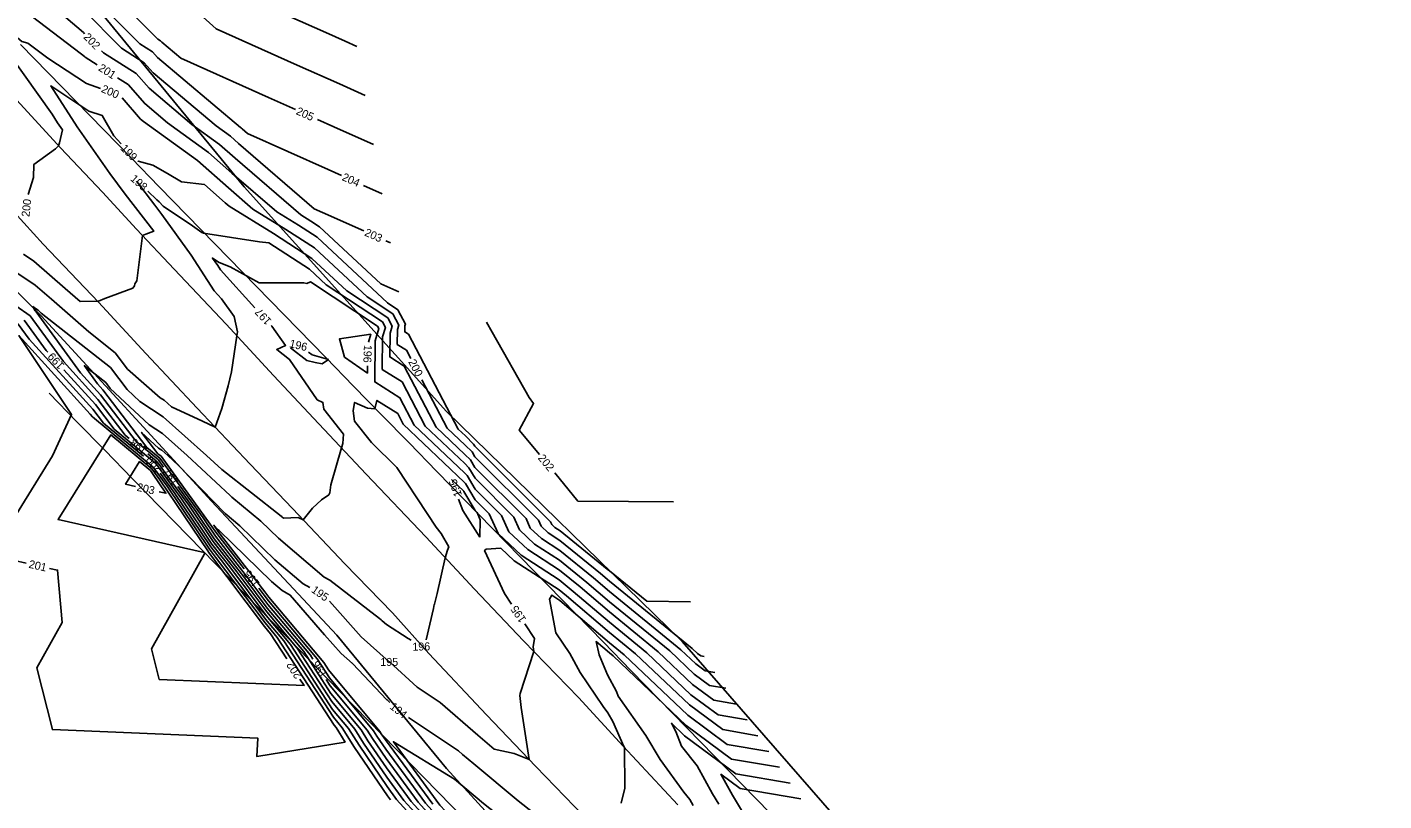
# Model space of a CAD drawing. Extents: x 2086416 to 2115205, y 575507 to 632762.
# Drawn here: x 2110120.8 to 2110459.9, y 582081.1 to 582274.4 of the extents above; entities that cross this region are included whole.
import ezdxf

# ---------------------------------------------------------------- set-up
doc = ezdxf.new("R2010")
doc.units = 0
for name, color, linetype in [('DTM Contours Major', 7, 'Continuous'), ('DTM Contours Major Text', 7, 'Continuous'), ('DTM Contours Minor', 7, 'Continuous'), ('DTM Contours Minor Text', 7, 'Continuous'), ('Exist Hydrographic FEMA Cross Section', 7, 'Continuous'), ('Exist Roads EOP', 7, 'Continuous'), ('Exist Vegetation Woods Line', 7, 'Continuous')]:
    doc.layers.add(name, color=color, linetype=linetype)

msp = doc.modelspace()

# ---------------------------------------------------------------- linework, layer by layer
at = {"layer": 'DTM Contours Major'}
for points in [[(2110109.16, 582313.08), (2110112.32, 582311.02), (2110129.31, 582294.29), (2110131.09, 582292.62), (2110132.72, 582292.09), (2110134.17, 582290.85), (2110153.5, 582271.34), (2110154.17, 582270.92), (2110154.43, 582270.61), (2110159.2, 582266.6), (2110181.16, 582256.77), (2110187.89, 582253.76)], [(2110139.1, 582259.08), (2110135.66, 582260.25), (2110126, 582266.59), (2110120.98, 582270.39), (2110119.48, 582270.82), (2110107.88, 582280.62), (2110107.79, 582280.67), (2110107.65, 582280.8), (2110106.39, 582281.73), (2110107.13, 582280.82), (2110107.89, 582279.73), (2110116.56, 582267.38), (2110127.02, 582252.6), (2110128.41, 582250.45), (2110129.6, 582248.74), (2110128.93, 582245.49), (2110128.68, 582244.73), (2110127.92, 582243.98), (2110122.51, 582240.09), (2110122.35, 582236.81), (2110121.07, 582232.55)], [(2110216.68, 582191.59), (2110215.58, 582193.69), (2110213.31, 582195.12), (2110213.35, 582198.82), (2110213.67, 582199.92), (2110212.19, 582202.73), (2110205.75, 582206.99), (2110192.62, 582219.23), (2110185.46, 582223.85), (2110177.23, 582228.94), (2110171.12, 582234.2), (2110163.38, 582241.04), (2110149.85, 582250.84), (2110149.16, 582251.42), (2110144.51, 582256.72)], [(2110193.36, 582251.31), (2110197.45, 582249.48), (2110207.4, 582245.02)], [(2110086.65, 582243.38), (2110095.68, 582232.16), (2110101, 582226.63), (2110106.9, 582218.72), (2110109.82, 582215.75), (2110111.89, 582209.48), (2110116.13, 582201.87), (2110118.59, 582200.15), (2110121.31, 582196.4), (2110137.22, 582178.92), (2110139.86, 582175.47), (2110149.85, 582167.21)], [(2110290, 582117.14), (2110289.15, 582117.29), (2110288.34, 582117.88), (2110287.04, 582119.12), (2110266.32, 582135.96), (2110264.06, 582137.88), (2110253.94, 582146.12), (2110251, 582148.03), (2110249.23, 582149.7), (2110248.56, 582151.2), (2110232.69, 582167.05), (2110231.99, 582168.26), (2110230.29, 582169.96), (2110225.81, 582174.22), (2110219.47, 582186.28)], [(2110191.46, 582134.37), (2110189.8, 582135.29), (2110182.74, 582141.3), (2110173.98, 582149.79), (2110170.26, 582152.86), (2110158.63, 582164.85), (2110155.96, 582167.33), (2110154.43, 582168.68), (2110153.61, 582169.23), (2110149.41, 582173.13), (2110153.47, 582167.82), (2110154.26, 582167.17), (2110166.58, 582150.21), (2110168.17, 582147.85), (2110175.02, 582139.02)], [(2110154.04, 582162.97), (2110157.57, 582158.11), (2110166.69, 582144.59), (2110169.67, 582140.76), (2110180.39, 582126.46), (2110184.93, 582121.05), (2110197.34, 582101.97), (2110199.56, 582099.31), (2110202.62, 582094.39), (2110210.86, 582082.32), (2110211.34, 582081.67), (2110211.64, 582081.34)], [(2110233.92, 582146.96), (2110234.05, 582151.33), (2110233.23, 582153.16), (2110232.79, 582153.6), (2110229.98, 582158.41), (2110229.95, 582158.44), (2110226.85, 582161.39)], [(2110228.63, 582156.43), (2110229.67, 582153.63), (2110233.92, 582146.96)], [(2110303.45, 582097.38), (2110294.64, 582098.89), (2110286.31, 582105.05), (2110272.88, 582117.83), (2110266.32, 582123.16), (2110255.61, 582132.3), (2110253.76, 582133.81), (2110242.54, 582141.09), (2110239.17, 582144.26), (2110235.48, 582144.01), (2110235.12, 582143.67), (2110240.07, 582132.89), (2110241.85, 582130.25)], [(2110178.7, 582134.27), (2110181.09, 582131.08), (2110193.25, 582116.59), (2110196.34, 582111.83), (2110207.38, 582098.6), (2110208.2, 582097.27), (2110210.42, 582094.03), (2110220.36, 582080.52), (2110224.5, 582075.98), (2110233.47, 582064.23), (2110239.72, 582055.18)], [(2110245.21, 582125.28), (2110247.64, 582121.68), (2110247.24, 582119.54), (2110247.42, 582118.38), (2110244.01, 582107.89), (2110243.92, 582107.4), (2110244.29, 582104.39), (2110246.27, 582091.41), (2110242.5, 582092.91), (2110237.49, 582094.05), (2110233.41, 582097.47), (2110224, 582105.68), (2110218.29, 582109.52), (2110211.34, 582115.8), (2110211.3, 582115.8), (2110211.29, 582115.81), (2110211.29, 582115.84), (2110204.27, 582122.09), (2110196.34, 582130.95)], [(2110211.34, 582115.8), (2110211.29, 582115.84)]]:
    msp.add_lwpolyline(points, dxfattribs=at)
at = {"layer": 'DTM Contours Minor'}
for points in [[(2110105.69, 582354.06), (2110078.26, 582335.67), (2110072.95, 582330.04), (2110076.03, 582327.3), (2110083.75, 582320.11), (2110086.59, 582317.64), (2110093.04, 582313.86), (2110096.74, 582314), (2110100.17, 582310.68), (2110110.46, 582303.98), (2110118.21, 582296.35), (2110124.17, 582290.79), (2110129.58, 582289.03), (2110134.41, 582284.9), (2110148.95, 582270.22), (2110152.13, 582268.2), (2110153.38, 582266.78), (2110174.1, 582249.31), (2110174.35, 582249.12), (2110174.5, 582248.99), (2110175.87, 582247.81), (2110196.04, 582238.78), (2110199.37, 582237.29)], [(2110088.26, 582344.86), (2110071.39, 582333.56), (2110068.12, 582330.1), (2110075.14, 582323.86), (2110080.32, 582319.04), (2110088.41, 582311.98), (2110093.09, 582309.23), (2110095.99, 582306.9), (2110107.74, 582298), (2110108.83, 582297.19), (2110116.85, 582289.32), (2110117.24, 582288.95), (2110126.44, 582285.97), (2110134.65, 582278.95), (2110144.41, 582269.09), (2110150.09, 582265.48), (2110152.32, 582262.94), (2110168.03, 582249.69), (2110171.61, 582247.1), (2110173.66, 582245.29), (2110192.55, 582229.02), (2110194.63, 582228.09), (2110204.98, 582223.46)], [(2110070.82, 582335.67), (2110064.52, 582331.45), (2110063.29, 582330.15), (2110074.25, 582320.42), (2110076.9, 582317.96), (2110084.69, 582311.16), (2110089.77, 582305.9), (2110093.79, 582302.67), (2110100.55, 582297.54), (2110108.44, 582291.73), (2110114.07, 582286.19), (2110116.66, 582284.86), (2110121.29, 582283.56), (2110123.31, 582282.91), (2110134.88, 582273), (2110135.16, 582272.72)], [(2110150.46, 582311.41), (2110150.06, 582290.18), (2110168.03, 582273.97), (2110188.32, 582264.9), (2110198.85, 582260.18), (2110205.3, 582257.29)], [(2110178.18, 582290.91), (2110178.06, 582284.52), (2110186.24, 582277.15), (2110195.47, 582273.02), (2110200.26, 582270.87), (2110203.2, 582269.56)], [(2110138.33, 582264.93), (2110135.33, 582266.84), (2110135.12, 582267.04), (2110134.42, 582267.65), (2110121.82, 582277.17)], [(2110139.38, 582268.46), (2110139.87, 582267.96), (2110148.05, 582262.77), (2110151.27, 582259.1), (2110161.97, 582250.07), (2110168.87, 582245.08), (2110172.81, 582241.6), (2110189.18, 582227.5), (2110191.7, 582225.94), (2110193.9, 582224.52), (2110209.23, 582210.23), (2110213.72, 582208.22)], [(2110144.27, 582245.25), (2110142.48, 582247.2), (2110139.57, 582252.28), (2110136.21, 582253.42), (2110126.7, 582259.67), (2110133.3, 582249.49), (2110141.43, 582237.79), (2110145.31, 582232.68), (2110152.45, 582223.39), (2110150.46, 582222.65), (2110149.62, 582222.32), (2110148.2, 582210.96), (2110147.68, 582210.21), (2110147.61, 582209.79), (2110147.18, 582209.14), (2110140.18, 582206.61), (2110138.64, 582205.95), (2110138.54, 582205.84), (2110138.27, 582205.9), (2110134.03, 582205.85), (2110130.31, 582209.12), (2110122.45, 582215.91), (2110119.87, 582217.62)], [(2110286.6, 582130.83), (2110275.64, 582130.94), (2110266.32, 582138.52), (2110265.75, 582139), (2110253.98, 582148.59), (2110252.69, 582149.42), (2110251.92, 582150.15), (2110251.63, 582150.81), (2110232.67, 582169.74), (2110232.39, 582170.23), (2110230.35, 582172.26), (2110228.56, 582173.97), (2110216.12, 582197.65), (2110215.19, 582198.24), (2110215.21, 582199.75), (2110215.34, 582200.19), (2110213.48, 582203.74), (2110210.84, 582205.48), (2110193.26, 582221.88), (2110188.58, 582224.89), (2110183.2, 582228.22), (2110171.96, 582237.9), (2110166.12, 582243.06), (2110155.91, 582250.46), (2110150.21, 582255.26), (2110146.01, 582260.05), (2110143.39, 582261.71)], [(2110292.69, 582113.19), (2110290.24, 582113.61), (2110287.93, 582115.32), (2110284.21, 582118.86), (2110266.32, 582133.4), (2110262.37, 582136.77), (2110253.91, 582143.66), (2110249.31, 582146.65), (2110246.54, 582149.25), (2110245.5, 582151.59), (2110232.71, 582164.36), (2110231.58, 582166.29), (2110230.22, 582167.65), (2110223.06, 582174.47), (2110215.05, 582189.72), (2110211.44, 582192), (2110211.49, 582197.9), (2110212, 582199.64), (2110210.91, 582201.73), (2110200.66, 582208.49), (2110191.98, 582216.59), (2110182.34, 582222.81), (2110171.26, 582229.66), (2110170.27, 582230.51), (2110165.12, 582235.06), (2110159.34, 582235.73), (2110155.89, 582237.85), (2110152.24, 582239.91), (2110148.54, 582240.92), (2110148.47, 582240.98)], [(2110148.15, 582235.89), (2110152.7, 582229.89), (2110154.49, 582227.57), (2110161.76, 582217.45), (2110167.51, 582208.51), (2110169.37, 582206.47), (2110172.55, 582202.06), (2110173.38, 582198.29), (2110173.24, 582197.24), (2110171.86, 582188.28), (2110171.08, 582184.8), (2110169.43, 582179.09), (2110167.82, 582174.41), (2110164.62, 582175.97), (2110156.87, 582179.5), (2110155.01, 582181.15), (2110154.03, 582181.8), (2110145.89, 582188.97), (2110142.78, 582193.04), (2110136.2, 582198.22), (2110126.91, 582206.38), (2110122.81, 582209.92), (2110112.15, 582217)], [(2110295.38, 582109.24), (2110291.34, 582109.93), (2110287.53, 582112.75), (2110281.38, 582118.6), (2110266.32, 582130.84), (2110260.68, 582135.65), (2110253.87, 582141.2), (2110247.62, 582145.26), (2110243.85, 582148.79), (2110242.43, 582151.98), (2110232.73, 582161.67), (2110231.18, 582164.32), (2110230.15, 582165.35), (2110220.31, 582174.72), (2110214.51, 582185.76), (2110209.56, 582188.88), (2110209.63, 582196.97), (2110210.34, 582199.37), (2110209.63, 582200.72), (2110195.57, 582209.99), (2110191.34, 582213.94), (2110181.24, 582220.46), (2110178.88, 582220.72), (2110164.9, 582222.92), (2110164.47, 582223.08), (2110162.14, 582224.71), (2110154.79, 582229.64), (2110153.76, 582230.71), (2110153.19, 582231.26), (2110150.97, 582233.41)], [(2110204.84, 582234.84), (2110209.51, 582232.75)], [(2110210.45, 582221.01), (2110211.61, 582220.49)], [(2110298.07, 582105.29), (2110292.44, 582106.25), (2110287.12, 582110.18), (2110278.54, 582118.34), (2110266.32, 582128.28), (2110258.99, 582134.53), (2110253.83, 582138.74), (2110245.92, 582143.87), (2110241.16, 582148.34), (2110239.36, 582152.37), (2110232.75, 582158.98), (2110230.78, 582162.35), (2110230.08, 582163.05), (2110217.56, 582174.97), (2110213.98, 582181.8), (2110207.68, 582185.76), (2110207.77, 582196.04), (2110208.67, 582199.09), (2110208.35, 582199.71), (2110191.62, 582210.75), (2110190.71, 582210.36), (2110189.95, 582210.48), (2110178.78, 582210.49), (2110171.53, 582214.5), (2110168.77, 582215.54), (2110167.12, 582216.69), (2110168.44, 582214.85), (2110169.14, 582213.76), (2110177.74, 582204.29)], [(2110117.94, 582204.78), (2110121.58, 582202.24), (2110129.85, 582190.82), (2110138.49, 582181.33), (2110145.31, 582172.41), (2110146.3, 582171.58)], [(2110181.77, 582199.85), (2110181.92, 582199.69), (2110185.41, 582194.85), (2110183.17, 582193.83), (2110186.37, 582191.37), (2110193.32, 582181.3), (2110194.74, 582180.62), (2110194.95, 582178.95), (2110199.87, 582172.71), (2110199.74, 582170.4), (2110199.37, 582169.27), (2110196.67, 582160), (2110196.41, 582158.03), (2110196.23, 582157.56), (2110194.4, 582156.32), (2110192.08, 582154.24), (2110189.75, 582151.3), (2110188.52, 582151.87), (2110184.89, 582151.74), (2110184.49, 582152.08), (2110184.42, 582152.15), (2110184.3, 582152.25), (2110169.43, 582163.86), (2110165.64, 582167.38), (2110154.82, 582176.99), (2110149, 582180.87), (2110145.76, 582183.88), (2110141.61, 582189.31), (2110124.29, 582202.95), (2110123.52, 582203.63), (2110123.17, 582203.93), (2110122.23, 582204.56), (2110122.77, 582203.5), (2110123.07, 582203.29), (2110134.13, 582188.02), (2110139.13, 582182.53), (2110148.03, 582170.88), (2110153.6, 582166.27), (2110154.91, 582164.47)], [(2110120.09, 582201.2), (2110125.58, 582193.61), (2110125.95, 582193.21)], [(2110235.58, 582200.71), (2110237.04, 582198.16), (2110246.25, 582181.86), (2110247.35, 582180.34), (2110243.79, 582173.72), (2110248.85, 582167.62)], [(2110198, 582099.45), (2110197.53, 582100), (2110183.27, 582121.94), (2110180.25, 582125.54), (2110167.91, 582142), (2110166.4, 582143.94), (2110155.77, 582159.69), (2110152.29, 582164.48), (2110137.14, 582177), (2110136.59, 582177.72), (2110118.74, 582197.32), (2110131.92, 582177.57), (2110127.14, 582167.29), (2110111.7, 582142.48), (2110120.58, 582140.49)], [(2110200.12, 582191.93), (2110198.83, 582196.54), (2110206.67, 582197.67), (2110206.09, 582195.7)], [(2110186.64, 582194.25), (2110190.71, 582191.11)], [(2110190.71, 582191.11), (2110192.75, 582190.64), (2110194.54, 582190.3), (2110196.08, 582191.33), (2110192.07, 582192.49), (2110191.1, 582193.18)], [(2110205.87, 582189.73), (2110205.85, 582187.95), (2110200.12, 582191.93)], [(2110129.99, 582188.77), (2110137.86, 582180.13), (2110142.58, 582173.94), (2110152.95, 582165.38), (2110159.37, 582156.53), (2110166.99, 582145.24), (2110171.43, 582139.52), (2110180.53, 582127.38), (2110186.6, 582120.16), (2110197.14, 582103.95), (2110201.12, 582099.16), (2110203.74, 582094.97), (2110210.77, 582084.66), (2110213.14, 582081.44), (2110222.72, 582070.93), (2110225.66, 582067.07), (2110236.67, 582051.15), (2110214.22, 582039.54)], [(2110216.79, 582121.22), (2110216.05, 582121.67), (2110210.62, 582125.15), (2110209.52, 582126.06), (2110209.52, 582126.06), (2110209.24, 582126.3), (2110208.9, 582126.68), (2110196.45, 582136.19), (2110195.04, 582136.98), (2110183.61, 582146.69), (2110179.2, 582150.97), (2110171.95, 582156.97), (2110171.57, 582157.35), (2110160.8, 582167.35), (2110154.62, 582172.84), (2110151.31, 582175.05), (2110141.57, 582184.1), (2110140.44, 582185.58), (2110135.1, 582189.79), (2110138.4, 582185.23), (2110139.76, 582183.73), (2110150.75, 582169.35), (2110153.93, 582166.72), (2110164.78, 582151.79), (2110167.87, 582147.2), (2110176.71, 582135.81), (2110180.95, 582130.15), (2110191.59, 582117.48), (2110192.24, 582116.48)], [(2110300.76, 582101.34), (2110293.54, 582102.57), (2110286.71, 582107.62), (2110275.71, 582118.09), (2110266.32, 582125.72), (2110257.3, 582133.42), (2110253.79, 582136.27), (2110244.23, 582142.48), (2110238.48, 582147.89), (2110236.3, 582152.77), (2110232.77, 582156.29), (2110230.38, 582160.38), (2110230.02, 582160.74), (2110214.81, 582175.22), (2110213.44, 582177.83), (2110208.22, 582181.12), (2110207.69, 582179.06), (2110205.89, 582179.18), (2110202.62, 582180.63), (2110202.32, 582178.51), (2110202.63, 582175.96), (2110206.85, 582170.62), (2110213.18, 582164.35), (2110220.8, 582152.86), (2110223.04, 582149.46), (2110224.29, 582147.92), (2110226.16, 582144.56), (2110225.87, 582143.7), (2110225.27, 582141.82), (2110223.28, 582132.9), (2110222.58, 582130.23), (2110222.57, 582130.16), (2110222.56, 582130.13), (2110222.38, 582129.14), (2110220.55, 582121.33)], [(2110181.61, 582122.84), (2110180.11, 582124.62), (2110166.14, 582143.24), (2110166.1, 582143.29), (2110153.97, 582161.27), (2110151.96, 582164.03), (2110141.71, 582172.5), (2110128.55, 582151.34), (2110165.07, 582143.15), (2110165.1, 582142.79), (2110151.87, 582119.09), (2110153.82, 582111.44), (2110190.02, 582109.89), (2110188.96, 582111.53)], [(2110152.17, 582162.85), (2110151.64, 582163.58), (2110148.91, 582165.84), (2110145.4, 582160.2), (2110147.92, 582159.64)], [(2110150.93, 582167.76), (2110153.27, 582165.82), (2110161.17, 582154.95), (2110167.28, 582145.9), (2110173.19, 582138.29), (2110180.67, 582128.31), (2110188.26, 582119.27), (2110196.94, 582105.92), (2110202.69, 582099.02), (2110204.85, 582095.54), (2110210.68, 582087), (2110214.95, 582081.21), (2110223.16, 582072.19), (2110227.61, 582066.36), (2110241.27, 582046.6), (2110242.14, 582045.61), (2110244.26, 582042.28), (2110214.02, 582011.24)], [(2110153.77, 582158.32), (2110155.48, 582157.94), (2110152.17, 582162.85)], [(2110252.68, 582163), (2110258.47, 582156), (2110271.1, 582155.87), (2110282.37, 582155.76)], [(2110158.44, 582159.61), (2110162.98, 582153.37), (2110167.58, 582146.55), (2110174.95, 582137.05), (2110180.81, 582129.23), (2110189.92, 582118.37), (2110196.74, 582107.89), (2110204.25, 582098.88), (2110205.97, 582096.12), (2110210.59, 582089.35), (2110216.75, 582080.98), (2110223.61, 582073.45), (2110229.57, 582065.65), (2110241.24, 582048.76), (2110244.31, 582045.24), (2110251.86, 582033.4), (2110241.09, 582022.35), (2110222.86, 582001.98)], [(2110211.44, 582105.68), (2110210.75, 582106.3), (2110210.73, 582106.3), (2110202.09, 582115.38), (2110202.08, 582115.39), (2110202.09, 582115.4), (2110199.29, 582117.88), (2110195.08, 582122.59), (2110186.55, 582132.5), (2110184.56, 582133.61), (2110181.86, 582135.9), (2110168.76, 582148.6), (2110168.57, 582148.76), (2110167.43, 582149.94), (2110168.38, 582148.63), (2110168.46, 582148.5), (2110180.23, 582133.34), (2110181.24, 582132), (2110194.91, 582115.69), (2110196.14, 582113.8), (2110208.94, 582098.45), (2110209.32, 582097.85), (2110210.33, 582096.37), (2110222.16, 582080.29)], [(2110126.43, 582139.17), (2110128.4, 582138.73), (2110129.52, 582125.69), (2110123.2, 582114.37), (2110127.13, 582098.91), (2110178.47, 582096.72), (2110178.22, 582092.14), (2110200.27, 582095.79), (2110198, 582099.45)], [(2110306.13, 582093.43), (2110295.73, 582095.21), (2110285.9, 582102.48), (2110270.05, 582117.57), (2110266.32, 582120.6), (2110253.92, 582131.18), (2110253.72, 582131.35), (2110251.95, 582132.49), (2110251.31, 582131.47), (2110252.95, 582123.09), (2110256.44, 582117.95), (2110259.04, 582113.13), (2110264.79, 582104.69), (2110265.93, 582103.07), (2110267.2, 582100.94), (2110269.96, 582094.66), (2110270.11, 582094.43), (2110270.15, 582084.25), (2110269.26, 582080.53)], [(2110185.68, 582116.56), (2110181.61, 582122.84)], [(2110308.82, 582089.48), (2110296.83, 582091.53), (2110285.49, 582099.92), (2110267.22, 582117.31), (2110266.32, 582118.04), (2110262.99, 582120.89), (2110263.79, 582117.57), (2110265.83, 582112.58), (2110268.06, 582108.45), (2110268.5, 582107.27), (2110275.42, 582097.4), (2110278.98, 582091.44), (2110284.96, 582083.29), (2110286.44, 582081.48), (2110287.22, 582079.93)], [(2110195.51, 582111.45), (2110196.54, 582109.86), (2110205.81, 582098.74), (2110207.08, 582096.7), (2110210.51, 582091.69), (2110218.55, 582080.75), (2110224.05, 582074.71), (2110231.52, 582064.94), (2110241.21, 582050.92), (2110246.49, 582044.86), (2110254.2, 582032.77), (2110254.23, 582032.74), (2110256.28, 582030.31), (2110264.15, 582018.43), (2110254.35, 582019.56), (2110220.3, 581977.38), (2110206.86, 581962.37)], [(2110247.4, 582078), (2110243.48, 582081.11), (2110232.4, 582090.33), (2110229.6, 582092.68), (2110228.58, 582093.57), (2110216.12, 582101.96)], [(2110311.51, 582085.53), (2110297.93, 582087.85), (2110285.08, 582097.35), (2110281.81, 582100.47), (2110282.92, 582098.41), (2110284.3, 582094.72), (2110288.25, 582089.85), (2110292.08, 582082.87), (2110293.64, 582080.28)], [(2110239.63, 582076.69), (2110234.85, 582080.48), (2110227.63, 582086.48), (2110212.34, 582095.86), (2110223.97, 582080.06), (2110225.38, 582078.5), (2110237.38, 582062.8), (2110241.12, 582057.39), (2110253.02, 582043.75), (2110256.71, 582037.96), (2110256.86, 582037.78), (2110266.82, 582025.99), (2110275.38, 582013.07), (2110279.92, 582006.23), (2110285.03, 581998.78), (2110298.39, 581976.04), (2110298.49, 581975.89), (2110298.8, 581975.39), (2110299.81, 581973.62), (2110296.89, 581973.45), (2110283.89, 581972.66)], [(2110314.2, 582081.58), (2110299.03, 582084.17), (2110294.18, 582087.76), (2110297.06, 582082.5), (2110300.58, 582076.68)]]:
    msp.add_lwpolyline(points, dxfattribs=at)
at = {"layer": 'Exist Hydrographic FEMA Cross Section'}
for points in [[(2110306.46, 582078.04), (2110299.52, 582085.15), (2110292.58, 582092.26), (2110285.65, 582099.37), (2110278.7, 582106.49), (2110271.77, 582113.6), (2110264.83, 582120.71), (2110257.89, 582127.82), (2110250.95, 582134.94), (2110244.01, 582142.05), (2110237.07, 582149.16), (2110230.14, 582156.27), (2110223.19, 582163.38), (2110216.26, 582170.5), (2110209.32, 582177.61), (2110202.38, 582184.72), (2110195.44, 582191.83), (2110188.5, 582198.95), (2110181.56, 582206.06), (2110174.62, 582213.17), (2110167.68, 582220.28), (2110160.74, 582227.39), (2110153.81, 582234.51), (2110146.86, 582241.62), (2110139.93, 582248.73), (2110132.99, 582255.84), (2110126.05, 582262.96), (2110119.11, 582270.07)], [(2110230.4, 582076.22), (2110223.46, 582083.33), (2110216.53, 582090.44), (2110209.58, 582097.55), (2110202.65, 582104.66), (2110195.71, 582111.78), (2110188.77, 582118.89), (2110181.83, 582126), (2110174.89, 582133.11), (2110167.95, 582140.23), (2110161.01, 582147.34), (2110154.07, 582154.45), (2110147.14, 582161.56), (2110140.2, 582168.68), (2110133.26, 582175.78), (2110126.32, 582182.9)]]:
    msp.add_lwpolyline(points, dxfattribs=at)
at = {"layer": 'Exist Roads EOP'}
for points in [[(2110283.42, 582080.08), (2110269.79, 582094.77), (2110258.57, 582106.89), (2110244.84, 582121.04), (2110232.61, 582133.97), (2110220.43, 582147.01), (2110205.56, 582162.74), (2110193.7, 582175.26), (2110182.38, 582187.32), (2110170.57, 582200.14), (2110157.55, 582213.9), (2110148.13, 582223.91), (2110139.67, 582233.18), (2110129.17, 582244.2), (2110118.25, 582256.11), (2110105.57, 582269.53), (2110093.37, 582282.59), (2110082.14, 582294.76), (2110071.88, 582305.53), (2110059.32, 582319.17)], [(2110044.03, 582306.54), (2110057.72, 582292.25), (2110067.42, 582282.08), (2110077.05, 582271.73), (2110082.67, 582265.54), (2110091.18, 582256.81), (2110101.9, 582244.92), (2110112.61, 582233.51), (2110124.83, 582220.15), (2110138.66, 582205.71), (2110150.44, 582192.87), (2110163.31, 582179.2), (2110176.51, 582165.18), (2110187.09, 582154.1), (2110200.16, 582140.29), (2110212.15, 582128.06), (2110221.2, 582117.92), (2110235.62, 582102.6), (2110247.94, 582089.65), (2110262.41, 582074.68), (2110272.71, 582063.48), (2110283.25, 582052.48)]]:
    msp.add_lwpolyline(points, dxfattribs=at)
at = {"layer": 'Exist Vegetation Woods Line'}
for points in [[(2110284.48, 582120.87), (2110225.58, 582178.38), (2110175.08, 582234.49), (2110136.61, 582281.24), (2110106.48, 582313.41), (2110078.56, 582339.36)], [(2110068.55, 582251.65), (2110094.73, 582231.68), (2110124.29, 582202.28), (2110166.88, 582155.97), (2110198.23, 582122.47), (2110225.6, 582089.15), (2110269.57, 582041.09)], [(2111059.79, 581657.65), (2110968.73, 581672.25), (2110864.06, 581705.25), (2110784.73, 581740.8), (2110702.3, 581784.67), (2110632.54, 581823.34), (2110568.48, 581865.95), (2110498.27, 581913.79), (2110441.66, 581966.78), (2110387.94, 582016.39), (2110334.43, 582063.69), (2110284.48, 582120.87)]]:
    msp.add_lwpolyline(points, dxfattribs=at)

# ---------------------------------------------------------------- texts
at = {"layer": 'DTM Contours Major Text'}
for s, rotation, p in [('200', 336.4209, (2110139.15, 582258.24)), ('205', 335.8814, (2110187.84, 582252.69)), ('200', 83.5266, (2110121.36, 582226.89)), ('200', 297.7124, (2110215.98, 582190.78)), ('200', 134.6269, (2110154.71, 582164.15)), ('195', 109.7652, (2110229.51, 582157.5)), ('195', 127.7584, (2110179.05, 582135.46)), ('195', 324.989, (2110191.65, 582133.39)), ('195', 124.0436, (2110245.63, 582126.44))]:
    msp.add_text(s, height=2, rotation=rotation, dxfattribs=at).set_placement(p)
msp.add_text('195', height=2, dxfattribs=at).set_placement((2110209.06, 582114.8))
at = {"layer": 'DTM Contours Minor Text'}
for s, rotation, p in [('202', 314.7306, (2110134.72, 582271.74)), ('201', 327.5741, (2110138.41, 582263.69)), ('199', 314.5413, (2110143.99, 582243.95)), ('198', 318.6348, (2110146.44, 582236.25)), ('204', 335.8846, (2110199.32, 582236.22)), ('203', 335.8846, (2110204.93, 582222.38)), ('197', 132.2462, (2110182.03, 582201.06)), ('196', 346.4707, (2110186.2, 582194.46)), ('199', 132.3216, (2110130.24, 582189.98)), ('196', 267.8759, (2110204.98, 582195.04)), ('198', 140.4308, (2110151.01, 582168.99)), ('202', 309.6491, (2110248.33, 582166.67)), ('197', 125.9879, (2110158.82, 582160.78)), ('203', 347.3513, (2110148.08, 582158.58)), ('201', 347.3513, (2110121.07, 582139.35)), ('196', 1.7073, (2110217.1, 582118.58)), ('202', 123.0288, (2110189.58, 582112.41)), ('196', 123.0288, (2110195.95, 582112.6)), ('194', 321.5276, (2110211.26, 582104.3))]:
    msp.add_text(s, height=2, rotation=rotation, dxfattribs=at).set_placement(p)

doc.saveas('drawing.dxf')
